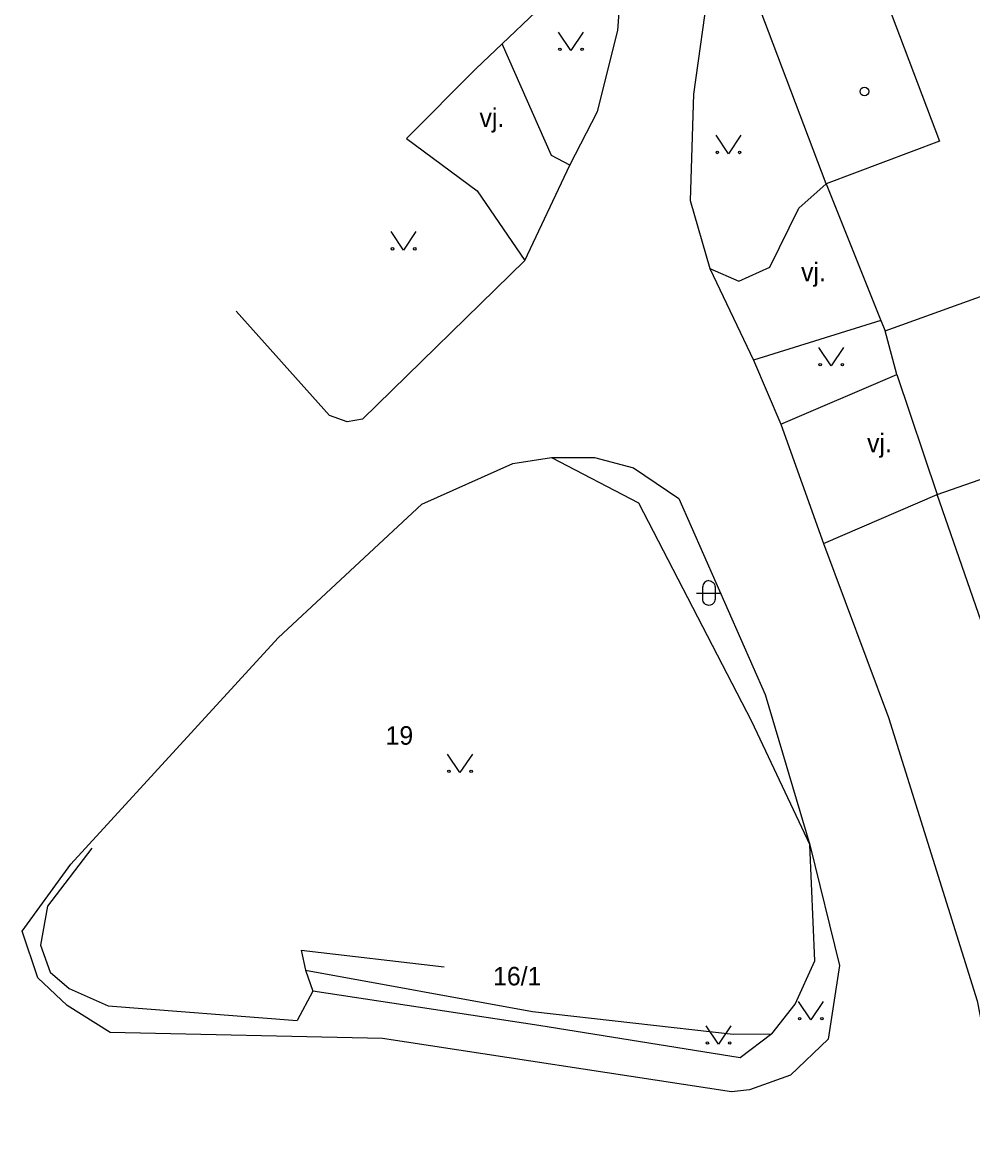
# Model space of a CAD drawing. Extents: x -836739 to -835945, y -1070775 to -1070126.
# Drawn here: x -836659.93 to -836621.48, y -1070320.31 to -1070275.32 of the extents above; entities that cross this region are included whole.
import ezdxf

# ---------------------------------------------------------------- set-up
doc = ezdxf.new("R2010")
doc.units = 0
for name, color, linetype in [('BodPole_mer', 7, 'Continuous'), ('Budovy_hranice', 7, 'Continuous'), ('Budovy_kody', 7, 'Continuous'), ('Doprava_hranice', 7, 'Continuous'), ('Doprava_kody', 7, 'Continuous'), ('Doprava_linie', 7, 'Continuous'), ('OstPloch_hranice', 7, 'Continuous'), ('OstPloch_kody', 7, 'Continuous'), ('RuianPar_popis', 7, 'Continuous'), ('Stavby_linie', 7, 'Continuous'), ('Zelen_kody', 7, 'Continuous')]:
    doc.layers.add(name, color=color, linetype=linetype)

msp = doc.modelspace()

# ---------------------------------------------------------------- linework, layer by layer
at = {"layer": 'BodPole_mer'}
for p, q in [((-836635.83, -1070275.65), (-836635.83, -1070275.65)), ((-836640.52, -1070276.19), (-836640.52, -1070276.19)), ((-836641.58, -1070277.2), (-836641.58, -1070277.2)), ((-836632.77, -1070278.23), (-836632.77, -1070278.23)), ((-836636.66, -1070278.93), (-836636.66, -1070278.93)), ((-836622.82, -1070280.13), (-836622.82, -1070280.13)), ((-836638.52, -1070280.72), (-836638.52, -1070280.72)), ((-836637.77, -1070281.1), (-836637.77, -1070281.1)), ((-836641.53, -1070282.14), (-836641.53, -1070282.14)), ((-836627.41, -1070281.86), (-836627.41, -1070281.86)), ((-836632.91, -1070282.53), (-836632.91, -1070282.53)), ((-836628.51, -1070282.85), (-836628.51, -1070282.85)), ((-836639.59, -1070284.96), (-836639.59, -1070284.96)), ((-836632.11, -1070285.29), (-836632.11, -1070285.29)), ((-836629.68, -1070285.23), (-836629.68, -1070285.23)), ((-836630.94, -1070285.8), (-836630.94, -1070285.8)), ((-836625.19, -1070287.39), (-836625.19, -1070287.39)), ((-836625.02, -1070287.81), (-836625.02, -1070287.81)), ((-836630.35, -1070289), (-836630.35, -1070289)), ((-836624.55, -1070289.58), (-836624.55, -1070289.58)), ((-836647.5, -1070291.24), (-836647.5, -1070291.24)), ((-836646.79, -1070291.49), (-836646.79, -1070291.49)), ((-836646.16, -1070291.38), (-836646.16, -1070291.38)), ((-836629.24, -1070291.58), (-836629.24, -1070291.58)), ((-836638.52, -1070292.93), (-836638.52, -1070292.93)), ((-836636.78, -1070292.94), (-836636.78, -1070292.94)), ((-836640.08, -1070293.18), (-836640.08, -1070293.18)), ((-836635.2, -1070293.36), (-836635.2, -1070293.36)), ((-836635, -1070294.77), (-836635, -1070294.77)), ((-836633.37, -1070294.59), (-836633.37, -1070294.59)), ((-836622.91, -1070294.43), (-836622.91, -1070294.43)), ((-836643.77, -1070294.82), (-836643.77, -1070294.82)), ((-836627.52, -1070296.42), (-836627.52, -1070296.42)), ((-836649.57, -1070300.23), (-836649.57, -1070300.23)), ((-836629.87, -1070302.53), (-836629.87, -1070302.53)), ((-836630.42, -1070303.6), (-836630.42, -1070303.6)), ((-836624.89, -1070303.46), (-836624.89, -1070303.46)), ((-836657.11, -1070308.75), (-836657.11, -1070308.75)), ((-836628.06, -1070308.61), (-836628.06, -1070308.61)), ((-836657.97, -1070309.39), (-836657.97, -1070309.39)), ((-836658.91, -1070311.1), (-836658.91, -1070311.1)), ((-836659.93, -1070312.1), (-836659.93, -1070312.1)), ((-836659.19, -1070312.67), (-836659.19, -1070312.67)), ((-836648.64, -1070312.88), (-836648.64, -1070312.88)), ((-836648.47, -1070313.69), (-836648.47, -1070313.69)), ((-836642.86, -1070313.55), (-836642.86, -1070313.55)), ((-836627.86, -1070313.3), (-836627.86, -1070313.3)), ((-836626.86, -1070313.5), (-836626.86, -1070313.5)), ((-836659.3, -1070313.99), (-836659.3, -1070313.99)), ((-836658.8, -1070313.76), (-836658.8, -1070313.76)), ((-836658.03, -1070314.42), (-836658.03, -1070314.42)), ((-836648.18, -1070314.53), (-836648.18, -1070314.53)), ((-836658.11, -1070315.12), (-836658.11, -1070315.12)), ((-836656.46, -1070315.13), (-836656.46, -1070315.13)), ((-836639.28, -1070315.36), (-836639.28, -1070315.36)), ((-836628.66, -1070315.06), (-836628.66, -1070315.06)), ((-836648.81, -1070315.72), (-836648.81, -1070315.72)), ((-836639.03, -1070315.92), (-836639.03, -1070315.92)), ((-836656.37, -1070316.2), (-836656.37, -1070316.2)), ((-836631.17, -1070316.28), (-836631.17, -1070316.28)), ((-836629.61, -1070316.26), (-836629.61, -1070316.26)), ((-836645.35, -1070316.45), (-836645.35, -1070316.45)), ((-836627.32, -1070316.48), (-836627.32, -1070316.48)), ((-836630.89, -1070317.23), (-836630.89, -1070317.23)), ((-836628.85, -1070317.93), (-836628.85, -1070317.93)), ((-836631.23, -1070318.61), (-836631.23, -1070318.61)), ((-836630.51, -1070318.53), (-836630.51, -1070318.53))]:
    msp.add_line(p, q, dxfattribs=at)
at = {"layer": 'Budovy_hranice'}
for points in [[(-836627.41, -1070281.86), (-836630.08, -1070274.8), (-836625.49, -1070273.06), (-836622.82, -1070280.13), (-836627.41, -1070281.86)], [(-836607.96, -1070306.22), (-836602.22, -1070304.21), (-836602.92, -1070302.12), (-836600.25, -1070301.18), (-836599.68, -1070302.84), (-836595.65, -1070301.45), (-836593.84, -1070307), (-836595.9, -1070307.68), (-836595.75, -1070308.17), (-836594.17, -1070313.02), (-836598.58, -1070314.46), (-836614.04, -1070320.04), (-836617.11, -1070311.18), (-836617.77, -1070309.29), (-836618.31, -1070307.72), (-836619.24, -1070305.03), (-836622.91, -1070294.43), (-836613.18, -1070291.04), (-836610.81, -1070297.91), (-836609.74, -1070297.52), (-836608.96, -1070299.76), (-836610.05, -1070300.14), (-836607.96, -1070306.22)]]:
    msp.add_lwpolyline(points, dxfattribs=at)
at = {"layer": 'Budovy_kody'}
msp.add_circle((-836625.86, -1070278.12), 0.175, dxfattribs=at)
at = {"layer": 'Doprava_hranice'}
for p, q in [((-836625.19, -1070287.39), (-836630.35, -1070289)), ((-836629.24, -1070291.58), (-836624.55, -1070289.58)), ((-836627.52, -1070296.42), (-836622.91, -1070294.43)), ((-836648.47, -1070313.69), (-836648.18, -1070314.53))]:
    msp.add_line(p, q, dxfattribs=at)
for points in [[(-836631.53, -1070271.72), (-836632.14, -1070273.69), (-836632.77, -1070278.23), (-836632.91, -1070282.53), (-836632.11, -1070285.29), (-836630.35, -1070289), (-836629.24, -1070291.58), (-836627.52, -1070296.42), (-836624.89, -1070303.46), (-836621.3, -1070314.92), (-836620.43, -1070319.36), (-836619.2, -1070321.11), (-836614.79, -1070322.41)], [(-836639.59, -1070284.96), (-836637.77, -1070281.1), (-836636.66, -1070278.93), (-836635.83, -1070275.65), (-836635.58, -1070272.1)], [(-836637.77, -1070281.1), (-836638.52, -1070280.72), (-836640.52, -1070276.19)], [(-836644.38, -1070280.02), (-836641.53, -1070282.14), (-836639.59, -1070284.96)], [(-836632.11, -1070285.29), (-836630.94, -1070285.8), (-836629.68, -1070285.23), (-836628.51, -1070282.85), (-836627.41, -1070281.86)], [(-836639.59, -1070284.96), (-836646.16, -1070291.38), (-836646.79, -1070291.49), (-836647.5, -1070291.24), (-836651.28, -1070287.01)], [(-836630.51, -1070318.53), (-836631.23, -1070318.61), (-836645.35, -1070316.45), (-836656.37, -1070316.2), (-836658.11, -1070315.12), (-836659.3, -1070313.99), (-836659.93, -1070312.1), (-836657.97, -1070309.39), (-836649.57, -1070300.23), (-836643.77, -1070294.82), (-836640.08, -1070293.18), (-836638.52, -1070292.93), (-836636.78, -1070292.94), (-836635.2, -1070293.36), (-836633.37, -1070294.59), (-836629.87, -1070302.53), (-836628.06, -1070308.61), (-836626.86, -1070313.5), (-836627.32, -1070316.48), (-836628.85, -1070317.93), (-836630.51, -1070318.53)], [(-836648.64, -1070312.88), (-836648.47, -1070313.69), (-836639.28, -1070315.36), (-836631.17, -1070316.28), (-836629.61, -1070316.26), (-836628.66, -1070315.06), (-836627.86, -1070313.3), (-836628.06, -1070308.61)], [(-836629.61, -1070316.26), (-836630.89, -1070317.23), (-836639.03, -1070315.92), (-836648.18, -1070314.53), (-836648.81, -1070315.72)]]:
    msp.add_lwpolyline(points, dxfattribs=at)
at = {"layer": 'Doprava_linie'}
msp.add_lwpolyline([(-836657.11, -1070308.75), (-836658.91, -1070311.1), (-836659.19, -1070312.67), (-836658.8, -1070313.76), (-836658.03, -1070314.42), (-836656.46, -1070315.13), (-836648.81, -1070315.72)], dxfattribs=at)
at = {"layer": 'OstPloch_hranice'}
msp.add_lwpolyline([(-836638.52, -1070292.93), (-836635, -1070294.77), (-836630.42, -1070303.6), (-836628.06, -1070308.61)], dxfattribs=at)
at = {"layer": 'OstPloch_kody'}
for p, q in [((-836632.4, -1070298.67), (-836632.4, -1070298.17)), ((-836631.9, -1070298.17), (-836631.9, -1070298.67)), ((-836632.65, -1070298.42), (-836631.65, -1070298.42))]:
    msp.add_line(p, q, dxfattribs=at)
for points in [[(-836632.15, -1070297.92), (-836632.195, -1070297.924), (-836632.242, -1070297.938), (-836632.287, -1070297.961), (-836632.327, -1070297.993), (-836632.359, -1070298.033), (-836632.382, -1070298.078), (-836632.396, -1070298.125), (-836632.4, -1070298.17)], [(-836632.15, -1070297.92), (-836632.105, -1070297.924), (-836632.058, -1070297.938), (-836632.013, -1070297.961), (-836631.973, -1070297.993), (-836631.941, -1070298.033), (-836631.918, -1070298.078), (-836631.904, -1070298.125), (-836631.9, -1070298.17)], [(-836632.15, -1070298.92), (-836632.195, -1070298.916), (-836632.242, -1070298.902), (-836632.287, -1070298.879), (-836632.327, -1070298.847), (-836632.359, -1070298.807), (-836632.382, -1070298.762), (-836632.396, -1070298.715), (-836632.4, -1070298.67)], [(-836631.9, -1070298.67), (-836631.904, -1070298.715), (-836631.918, -1070298.762), (-836631.941, -1070298.807), (-836631.973, -1070298.847), (-836632.013, -1070298.879), (-836632.058, -1070298.902), (-836632.105, -1070298.916), (-836632.15, -1070298.92)]]:
    msp.add_lwpolyline(points, dxfattribs=at)
at = {"layer": 'RuianPar_popis'}
for p, q in [((-836645.23, -1070304.56), (-836645.23, -1070304.56)), ((-836640.88, -1070314.3), (-836640.88, -1070314.3))]:
    msp.add_line(p, q, dxfattribs=at)
at = {"layer": 'Stavby_linie'}
for p, q in [((-836641.58, -1070277.2), (-836644.38, -1070280.02)), ((-836624.55, -1070289.58), (-836625.02, -1070287.81)), ((-836624.55, -1070289.58), (-836622.91, -1070294.43)), ((-836648.64, -1070312.88), (-836642.86, -1070313.55))]:
    msp.add_line(p, q, dxfattribs=at)
for points in [[(-836641.58, -1070277.2), (-836640.52, -1070276.19), (-836636.43, -1070272.29), (-836636.64, -1070271.92)], [(-836625.02, -1070287.81), (-836612.71, -1070283.37), (-836602.62, -1070280.43), (-836601.08, -1070280.23), (-836599.46, -1070280.37), (-836597.02, -1070280.91), (-836595.56, -1070281.28), (-836594.54, -1070282.32), (-836594.03, -1070282.98), (-836593.26, -1070284.7), (-836590.24, -1070283.45)], [(-836627.41, -1070281.86), (-836625.19, -1070287.39), (-836625.02, -1070287.81)]]:
    msp.add_lwpolyline(points, dxfattribs=at)
at = {"layer": 'Zelen_kody'}
for points in [[(-836637.23, -1070275.72), (-836637.73, -1070276.47), (-836638.23, -1070275.72)], [(-836630.86, -1070279.89), (-836631.36, -1070280.64), (-836631.86, -1070279.89)], [(-836644, -1070283.79), (-836644.5, -1070284.54), (-836645, -1070283.79)], [(-836626.7, -1070288.48), (-836627.2, -1070289.23), (-836627.7, -1070288.48)], [(-836641.72, -1070304.94), (-836642.22, -1070305.69), (-836642.72, -1070304.94)], [(-836627.53, -1070314.95), (-836628.03, -1070315.7), (-836628.53, -1070314.95)], [(-836631.26, -1070315.93), (-836631.76, -1070316.68), (-836632.26, -1070315.93)]]:
    msp.add_lwpolyline(points, dxfattribs=at)
for centre in [(-836638.179, -1070276.42), (-836637.279, -1070276.42), (-836631.809, -1070280.59), (-836630.909, -1070280.59), (-836644.949, -1070284.49), (-836644.049, -1070284.49), (-836627.649, -1070289.18), (-836626.749, -1070289.18), (-836642.669, -1070305.64), (-836641.769, -1070305.64), (-836628.479, -1070315.65), (-836627.579, -1070315.65), (-836632.209, -1070316.63), (-836631.309, -1070316.63)]:
    msp.add_circle(centre, 0.05, dxfattribs=at)

# ---------------------------------------------------------------- texts
at = {"layer": 'Doprava_kody'}
for p in [(-836641.43, -1070279.56), (-836628.42, -1070285.8), (-836625.75, -1070292.72)]:
    msp.add_text('vj.', height=0.75, dxfattribs=at).set_placement(p)
at = {"layer": 'RuianPar_popis'}
for s, p in [('19', (-836645.23, -1070304.56)), ('16/1', (-836640.88, -1070314.3))]:
    msp.add_text(s, height=0.75, dxfattribs=at).set_placement(p)

doc.saveas('drawing.dxf')
